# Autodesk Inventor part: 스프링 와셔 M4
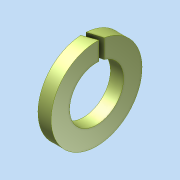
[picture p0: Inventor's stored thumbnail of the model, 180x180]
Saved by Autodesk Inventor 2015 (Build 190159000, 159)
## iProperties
Created: 2024-06
Part Number: 스프링 와셔 M4
Material: 일반
Document SubType Name: Modeling
Designer: Administrator
Density: 1 g/cm^3
Appearance: 기본값
Author: Administrator
Author: jhkim
Description: 스프링 잠금 와셔
Creation Date: 2024-05-29
Sending System: Autodesk Inventor 2025
Preprocessor: ST-DEVELOPER v20
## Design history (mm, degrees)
node "스프링 와셔 M41"
body "Solid1"
node "기준1"
